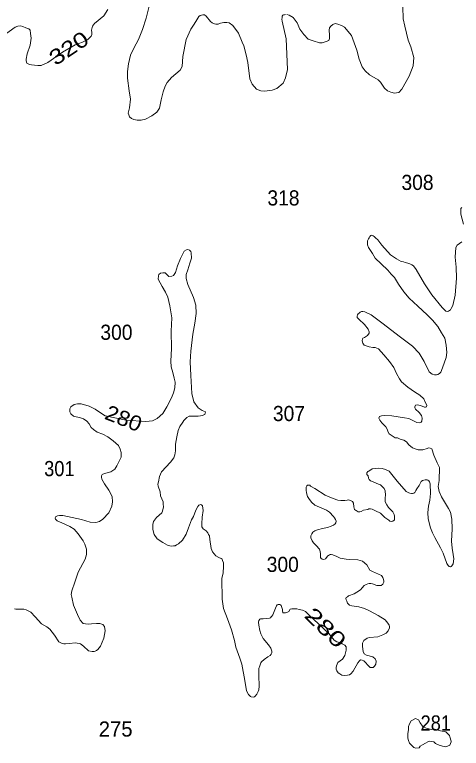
# Model space of a CAD drawing. Extents: x 445.4 to 500, y 8728.7 to 8784.
# Drawn here: x 488.21 to 492.93, y 8760.22 to 8767.97 of the extents above; entities that cross this region are included whole.
import ezdxf
from ezdxf.enums import TextEntityAlignment as Align

# ---------------------------------------------------------------- set-up
doc = ezdxf.new("R2010")
doc.units = 0
doc.header["$LTSCALE"] = 0.064
doc.layers.add('2', color=7, linetype='Continuous', lineweight=13)
doc.layers.add('21', color=7, linetype='Continuous')
doc.layers.add('61', color=7, linetype='Continuous')

msp = doc.modelspace()

# ---------------------------------------------------------------- linework, layer by layer
at = {"layer": '2'}
for points in [[(489.6381, 8768.086), (489.5993, 8767.9309), (489.5633, 8767.8091), (489.5185, 8767.7047), (489.4707, 8767.6136), (489.4334, 8767.5405), (489.414, 8767.4471), (489.402, 8767.365), (489.402, 8767.2949), (489.4214, 8767.1621), (489.435, 8767.0759), (489.4231, 8766.9819), (489.4111, 8766.9267), (489.4171, 8766.9073), (489.4246, 8766.8864), (489.444, 8766.8685), (489.4709, 8766.8581), (489.5067, 8766.8521), (489.5336, 8766.8521), (489.5485, 8766.8536), (489.5948, 8766.864), (489.662, 8766.8998), (489.7143, 8766.9357), (489.7427, 8766.9804), (489.7591, 8767.0669), (489.78, 8767.1505), (489.8013, 8767.2128), (489.8208, 8767.2516), (489.8686, 8767.3024), (489.9612, 8767.3814), (489.9821, 8767.4187), (489.9866, 8767.5232), (490.023, 8767.7048), (490.0708, 8767.8137), (490.1022, 8767.8555), (490.1261, 8767.8957), (490.1575, 8767.9465), (490.1694, 8767.9569), (490.1978, 8767.9659), (490.2157, 8767.9644), (490.2351, 8767.9509), (490.2799, 8767.8957), (490.2979, 8767.8793), (490.3232, 8767.8689), (490.3382, 8767.8674), (490.3606, 8767.8674), (490.3875, 8767.8763), (490.4024, 8767.8808), (490.4218, 8767.8838), (490.4353, 8767.8853), (490.4532, 8767.8853), (490.4786, 8767.8793), (490.5144, 8767.8525), (490.5742, 8767.7719), (490.616, 8767.6779), (490.6324, 8767.6391), (490.6578, 8767.5436), (490.6733, 8767.462), (490.6972, 8767.2874), (490.7196, 8767.2337), (490.7674, 8767.1785), (490.8107, 8767.1606), (490.8525, 8767.1591), (490.9332, 8767.1681), (490.9795, 8767.1875), (491.0467, 8767.2442), (491.0721, 8767.3009), (491.093, 8767.3889), (491.0855, 8767.5485), (491.0776, 8767.7107), (491.0358, 8767.8972), (491.0343, 8767.9181), (491.0358, 8767.9345), (491.0388, 8767.9494), (491.0448, 8767.9599), (491.0522, 8767.9643), (491.0627, 8767.9658), (491.0716, 8767.9673)], [(488.0492, 8767.7161), (488.2173, 8767.8364), (488.2441, 8767.8469), (488.274, 8767.8484), (488.2994, 8767.8424), (488.3293, 8767.829), (488.3606, 8767.8156), (488.3741, 8767.8021), (488.3801, 8767.7678), (488.3864, 8767.7191), (488.3744, 8767.646), (488.3431, 8767.5535), (488.3326, 8767.4953), (488.3341, 8767.4804), (488.3416, 8767.455), (488.367, 8767.4401), (488.3894, 8767.4356), (488.4207, 8767.4327), (488.4566, 8767.4312), (488.4924, 8767.4312), (488.5611, 8767.4625), (488.7165, 8767.5699), (488.8509, 8767.649), (488.9295, 8767.6752), (488.9833, 8767.7051), (489.0206, 8767.7394), (489.0251, 8767.7558), (489.0251, 8767.7782), (489.0236, 8767.8035), (489.0326, 8767.8438), (489.055, 8767.8751), (489.1521, 8767.9557), (489.1969, 8768.0214)], [(491.4316, 8767.6704), (491.46, 8767.6675), (491.5033, 8767.6824), (491.5287, 8767.6928), (491.5362, 8767.7152), (491.5362, 8767.751), (491.5332, 8767.8032), (491.5362, 8767.8271), (491.5496, 8767.8465), (491.5705, 8767.8629), (491.5974, 8767.8733), (491.6243, 8767.8659), (491.6631, 8767.8525), (491.6945, 8767.8345), (491.7677, 8767.7465), (491.8244, 8767.5929), (491.8505, 8767.495), (491.8819, 8767.4159), (491.9132, 8767.3741), (491.961, 8767.3309), (492.0506, 8767.2772), (492.076, 8767.2533), (492.1194, 8767.1921), (492.1507, 8767.1608), (492.186, 8767.1472), (492.2234, 8767.1383), (492.2443, 8767.1398), (492.2697, 8767.1457), (492.301, 8767.1786), (492.3787, 8767.3158), (492.419, 8767.4247), (492.4267, 8767.5134), (492.3968, 8767.6282), (492.3669, 8767.6983), (492.3311, 8767.846), (492.3161, 8767.9232), (492.3101, 8768.05)], [(491.0881, 8767.9688), (491.112, 8767.9629), (491.1523, 8767.9375), (491.1941, 8767.8793), (491.2225, 8767.8122), (491.2643, 8767.7555), (491.3121, 8767.7062), (491.3629, 8767.6898), (491.4316, 8767.6704)], [(492.9534, 8765.7557), (492.9253, 8765.8602), (492.9237, 8765.8836), (492.9237, 8765.8992), (492.9253, 8765.9179), (492.9347, 8765.9304)], [(492.5593, 8763.8564), (492.5453, 8763.8814), (492.5342, 8763.9106), (492.4905, 8763.9496), (492.4343, 8763.9839), (492.364, 8764.0323), (492.2969, 8764.09), (492.275, 8764.1196), (492.2438, 8764.1758), (492.2157, 8764.2397), (492.1701, 8764.3033), (492.1107, 8764.3735), (492.053, 8764.439), (492.0202, 8764.4515), (491.9936, 8764.453), (491.9546, 8764.4593), (491.9046, 8764.4749), (491.889, 8764.4983), (491.8859, 8764.5092), (491.8828, 8764.5263), (491.8859, 8764.5404), (491.889, 8764.5497), (491.9062, 8764.556), (491.9281, 8764.57), (491.939, 8764.5778), (491.9562, 8764.6043), (491.9562, 8764.6043), (491.9562, 8764.6184), (491.9437, 8764.6464), (491.9062, 8764.6932), (491.8453, 8764.7525), (491.8297, 8764.7696), (491.8281, 8764.7837), (491.8312, 8764.7961), (491.8406, 8764.8055), (491.85, 8764.8149), (491.8609, 8764.8242), (491.875, 8764.832), (491.889, 8764.832), (491.9109, 8764.8273), (491.9765, 8764.7977), (492.0904, 8764.7119), (492.2856, 8764.5591), (492.4152, 8764.464), (492.4845, 8764.3912), (492.5361, 8764.3054), (492.5891, 8764.1932), (492.6204, 8764.1682), (492.6469, 8764.162), (492.6656, 8764.1635), (492.6797, 8764.1651), (492.6984, 8764.176), (492.714, 8764.1916), (492.7312, 8764.2353), (492.7687, 8764.346), (492.7764, 8764.3987), (492.7702, 8764.4751), (492.7546, 8764.5484), (492.7187, 8764.6077), (492.6812, 8764.6747), (492.6265, 8764.7402), (492.5672, 8764.7979), (492.4714, 8764.8896), (492.3778, 8764.9723), (492.3216, 8765.0393), (492.2653, 8765.1189), (492.2232, 8765.1922), (492.1873, 8765.2265), (492.1545, 8765.267), (492.0838, 8765.3352), (492.0182, 8765.396), (491.9901, 8765.4459), (491.9495, 8765.5068), (491.9401, 8765.5348), (491.9386, 8765.5582), (491.9401, 8765.5785), (491.9479, 8765.5988), (491.9573, 8765.6112), (491.9636, 8765.6222), (491.9729, 8765.6346), (491.9854, 8765.6362), (491.9979, 8765.63), (492.0104, 8765.6222), (492.0245, 8765.6097), (492.0463, 8765.5879), (492.09, 8765.5333), (492.1829, 8765.431), (492.2453, 8765.3889), (492.2953, 8765.3608), (492.3187, 8765.3546), (492.3375, 8765.3484), (492.364, 8765.3421), (492.3859, 8765.3359), (492.4062, 8765.325), (492.4233, 8765.3125), (492.4514, 8765.2766), (492.5404, 8765.1253), (492.6162, 8765.0065), (492.7254, 8764.874), (492.766, 8764.8366), (492.7848, 8764.8334)], [(492.7848, 8764.8334), (492.7957, 8764.8366), (492.8144, 8764.849), (492.8144, 8764.849), (492.8207, 8764.8631), (492.841, 8764.8943), (492.866, 8765.0034), (492.88, 8765.1828), (492.8738, 8765.2994), (492.866, 8765.4054), (492.8722, 8765.5083), (492.8863, 8765.5317), (492.9331, 8765.5676)], [(488.9699, 8762.3213), (488.9539, 8762.3754), (488.9344, 8762.4083), (488.8818, 8762.4831), (488.8387, 8762.5325), (488.7941, 8762.5627), (488.7096, 8762.5994), (488.6602, 8762.6217), (488.6443, 8762.6376), (488.6411, 8762.6487), (488.6443, 8762.6615), (488.6554, 8762.6694), (488.6634, 8762.6726), (488.6841, 8762.6758), (488.7208, 8762.6758), (488.9162, 8762.6347), (489.0103, 8762.6077), (489.0693, 8762.6029), (489.1075, 8762.6156), (489.1426, 8762.6395), (489.2064, 8762.7064), (489.2382, 8762.7764), (489.2462, 8762.8226), (489.2398, 8762.8783), (489.2063, 8762.9448), (489.1617, 8763.0117), (489.1314, 8763.0594), (489.1282, 8763.0817), (489.1282, 8763.0945), (489.1362, 8763.1088), (489.1601, 8763.1199), (489.2287, 8763.139), (489.2701, 8763.1677), (489.2924, 8763.2027), (489.3355, 8763.2935), (489.337, 8763.3412), (489.3259, 8763.3779), (489.3081, 8763.4171), (489.2507, 8763.4648), (489.1949, 8763.5094), (489.1439, 8763.5349), (489.0818, 8763.5588), (489.0435, 8763.5843), (489.018, 8763.605), (488.9973, 8763.6463), (488.9734, 8763.675), (488.9399, 8763.6973), (488.9064, 8763.7084), (488.8331, 8763.7276), (488.806, 8763.7498), (488.7948, 8763.7721), (488.7948, 8763.8024), (488.8044, 8763.8263), (488.8395, 8763.8501), (488.8761, 8763.8581), (488.9144, 8763.8581), (488.9973, 8763.831), (489.0626, 8763.8008), (489.1168, 8763.761), (489.1678, 8763.7307), (489.391, 8763.6846), (489.5958, 8763.6705), (489.666, 8763.6769), (489.717, 8763.7008), (489.7776, 8763.7533), (489.819, 8763.8265), (489.8669, 8763.9217), (489.8908, 8763.9711), (489.902, 8764.0252), (489.9068, 8764.0857), (489.8956, 8764.1287), (489.8813, 8764.1876), (489.8653, 8764.2481), (489.8621, 8764.3086), (489.867, 8764.4403), (489.8638, 8764.625), (489.8734, 8764.7644), (489.8511, 8764.8933), (489.8303, 8764.9841), (489.8032, 8765.0366), (489.7698, 8765.0955), (489.7283, 8765.1748), (489.7299, 8765.2082), (489.7331, 8765.221), (489.7506, 8765.2353), (489.7761, 8765.2417), (489.7873, 8765.2417), (489.8001, 8765.2385), (489.8256, 8765.2146), (489.8399, 8765.2003), (489.8734, 8765.2066), (489.8734, 8765.2066), (489.8877, 8765.2114), (489.9116, 8765.2432), (489.9308, 8765.3149), (489.9626, 8765.3913), (490.0025, 8765.4677), (490.028, 8765.4821), (490.0392, 8765.4853), (490.0599, 8765.4789), (490.071, 8765.4662)], [(490.071, 8765.4662), (490.0758, 8765.4518), (490.0791, 8765.3937), (490.0632, 8765.3427), (490.0408, 8765.2727), (490.0233, 8765.2233), (490.0233, 8765.1803), (490.0393, 8765.1182), (490.0998, 8764.9797), (490.1263, 8764.8997), (490.1285, 8764.8115), (490.1136, 8764.7098), (490.0924, 8764.5932), (490.0733, 8764.4119), (490.0669, 8764.2996), (490.0733, 8764.1554), (490.0818, 8763.9657), (490.103, 8763.8767), (490.1497, 8763.8131), (490.1921, 8763.7856), (490.2261, 8763.7707), (490.2261, 8763.7707), (490.2197, 8763.7453), (490.2197, 8763.7453), (490.1921, 8763.7347), (490.173, 8763.7284), (490.1497, 8763.7262), (490.1178, 8763.7262), (490.086, 8763.7262), (490.0542, 8763.7262), (490.0287, 8763.7114), (489.9969, 8763.6796), (489.9863, 8763.6627), (489.9546, 8763.6174), (489.9393, 8763.5759), (489.9251, 8763.507), (489.9109, 8763.4306), (489.9087, 8763.3607), (489.9029, 8763.3174), (489.893, 8763.2879), (489.8591, 8763.2388), (489.764, 8763.1393), (489.741, 8763.0891), (489.7295, 8763.0335), (489.724, 8763.0095), (489.7262, 8762.9865), (489.747, 8762.9286), (489.7524, 8762.886), (489.7787, 8762.8216), (489.7809, 8762.7964), (489.782, 8762.768), (489.7743, 8762.7243), (489.7645, 8762.707), (489.711, 8762.6568), (489.6781, 8762.6153), (489.6694, 8762.5825), (489.6705, 8762.5279), (489.6847, 8762.4776), (489.7153, 8762.4318), (489.7755, 8762.3924), (489.8258, 8762.364), (489.8663, 8762.3542), (489.8892, 8762.3553), (489.9056, 8762.3575), (489.9209, 8762.3662), (489.9417, 8762.3793), (489.9855, 8762.4154), (490.0237, 8762.4809), (490.0489, 8762.5454), (490.0806, 8762.6328), (490.1016, 8762.6652), (490.1268, 8762.7329), (490.1465, 8762.7733), (490.1552, 8762.7854), (490.1673, 8762.7897), (490.1793, 8762.7919), (490.1793, 8762.7919), (490.1869, 8762.7876), (490.1946, 8762.7788), (490.199, 8762.7548), (490.2023, 8762.7318), (490.1935, 8762.659), (490.188, 8762.5891), (490.1902, 8762.5574), (490.2023, 8762.5377), (490.2329, 8762.517), (490.2529, 8762.4935), (490.2606, 8762.4782), (490.2682, 8762.4608), (490.2737, 8762.4247), (490.2857, 8762.3286), (490.3021, 8762.2925), (490.3196, 8762.2707), (490.3382, 8762.2499), (490.3678, 8762.2324), (490.3929, 8762.2237), (490.4028, 8762.2161), (490.4082, 8762.203), (490.4159, 8762.1789), (490.4192, 8762.1376), (490.4126, 8762.0732)], [(492.4131, 8762.9105), (492.4293, 8762.9146), (492.4385, 8762.9217), (492.4506, 8762.9399), (492.4598, 8762.9592), (492.4831, 8762.9937), (492.5035, 8763.0353), (492.5207, 8763.0454), (492.5492, 8763.0525), (492.5583, 8763.0546), (492.5685, 8763.0546), (492.5756, 8763.0505), (492.5857, 8763.0434), (492.5939, 8763.0322), (492.601, 8763.012), (492.605, 8762.9105), (492.5959, 8762.8405), (492.5812, 8762.7747), (492.5751, 8762.7079), (492.5787, 8762.6411), (492.6047, 8762.5469), (492.6243, 8762.4925), (492.651, 8762.4464), (492.7079, 8762.3364), (492.7382, 8762.2784), (492.7764, 8762.1705), (492.7915, 8762.1489), (492.7973, 8762.1432), (492.8023, 8762.1374), (492.8102, 8762.1338), (492.8138, 8762.1353), (492.8225, 8762.1381), (492.8297, 8762.1446), (492.8419, 8762.1662), (492.8491, 8762.2194), (492.8448, 8762.2651), (492.8333, 8762.3313), (492.8239, 8762.4075), (492.8312, 8762.5362), (492.8289, 8762.6379), (492.8152, 8762.7132), (492.7923, 8762.7497), (492.7216, 8762.8728), (492.6965, 8762.9321), (492.685, 8762.9845), (492.6942, 8763.0484), (492.6987, 8763.1829), (492.6756, 8763.2329), (492.638, 8763.3158), (492.6185, 8763.3819), (492.6004, 8763.3897), (492.5835, 8763.3936), (492.5689, 8763.3861), (492.5236, 8763.372), (492.4971, 8763.3705), (492.4736, 8763.3705), (492.4424, 8763.3798), (492.4127, 8763.3907), (492.3737, 8763.4219), (492.3501, 8763.4541), (492.3205, 8763.4712), (492.2845, 8763.4837), (492.2705, 8763.4915), (492.2564, 8763.4977), (492.2299, 8763.4977), (492.1674, 8763.5398), (492.1534, 8763.5632), (492.1487, 8763.5819), (492.1315, 8763.6147), (492.0894, 8763.6552), (492.0675, 8763.6849), (492.0597, 8763.7036), (492.0659, 8763.7223), (492.0659, 8763.7223), (492.0847, 8763.7285), (492.1128, 8763.7317), (492.1955, 8763.7301), (492.3283, 8763.7083), (492.3751, 8763.702), (492.4251, 8763.6771), (492.461, 8763.6584), (492.4828, 8763.6552), (492.5063, 8763.6646), (492.5063, 8763.6646), (492.5109, 8763.674), (492.5141, 8763.7036), (492.5078, 8763.7348), (492.4844, 8763.7644), (492.4454, 8763.8003), (492.4391, 8763.8128), (492.4391, 8763.8237), (492.4454, 8763.8424), (492.4454, 8763.8424), (492.4641, 8763.8455), (492.4969, 8763.8377), (492.539, 8763.8221), (492.5515, 8763.8206), (492.5609, 8763.8252), (492.5656, 8763.8393), (492.5656, 8763.8393), (492.5593, 8763.8564)], [(491.3617, 8762.5), (491.3832, 8762.5156), (491.4086, 8762.5253), (491.4642, 8762.541), (491.5143, 8762.5517), (491.5542, 8762.565), (491.5806, 8762.5762), (491.5979, 8762.5904), (491.604, 8762.6015), (491.607, 8762.6167), (491.5989, 8762.634), (491.5888, 8762.6512), (491.5776, 8762.6675), (491.538, 8762.7111), (491.5065, 8762.7324), (491.4303, 8762.7639), (491.3826, 8762.7862), (491.347, 8762.8166), (491.3204, 8762.8561), (491.3062, 8762.8794), (491.294, 8762.918), (491.2889, 8762.9443), (491.2889, 8762.9616), (491.29, 8762.9707), (491.291, 8762.9778), (491.2991, 8762.99), (491.3052, 8762.9961), (491.3113, 8762.9981), (491.3296, 8762.9961), (491.3377, 8762.9859), (491.383, 8762.962), (491.4907, 8762.891), (491.575, 8762.8565), (491.6248, 8762.8403), (491.6583, 8762.8362), (491.6979, 8762.8362), (491.7233, 8762.8403), (491.7375, 8762.8413), (491.7588, 8762.8372), (491.767, 8762.8332), (491.7791, 8762.8251), (491.7923, 8762.8058), (491.7944, 8762.7693), (491.7974, 8762.753), (491.8015, 8762.7419), (491.8106, 8762.7338), (491.8188, 8762.7297), (491.8411, 8762.7175), (491.858, 8762.7159), (491.8712, 8762.72), (491.8965, 8762.7322), (491.9423, 8762.7423), (491.9534, 8762.7474), (491.9687, 8762.7484), (491.9869, 8762.7433), (492.0245, 8762.7251), (492.0743, 8762.7027), (492.122, 8762.6551), (492.1627, 8762.6277), (492.1759, 8762.6175), (492.1931, 8762.6145), (492.2063, 8762.6175), (492.2185, 8762.6277), (492.2185, 8762.6277), (492.2226, 8762.6327), (492.2236, 8762.647), (492.2246, 8762.6693), (492.2185, 8762.6881), (492.2053, 8762.7155), (492.1617, 8762.7632), (492.1434, 8762.7916), (492.1292, 8762.8139), (492.1241, 8762.8251), (492.1241, 8762.8464), (492.1241, 8762.8626), (492.1281, 8762.8931), (492.1251, 8762.9377), (492.1158, 8762.9607), (492.0904, 8762.9881), (492.0772, 8763.0013), (492.0558, 8763.0084), (491.9969, 8763.0317), (491.9685, 8763.0439), (491.9563, 8763.0571), (491.9492, 8763.0713), (491.9441, 8763.0946), (491.9319, 8763.1119), (491.9329, 8763.1281), (491.9421, 8763.1403), (491.9522, 8763.1464), (491.9888, 8763.1697), (492.0579, 8763.1768), (492.0944, 8763.1738), (492.129, 8763.1646), (492.1676, 8763.1454), (492.2526, 8763.0414), (492.346, 8762.9318), (492.3765, 8762.9156), (492.3867, 8762.9115), (492.4029, 8762.9105), (492.4131, 8762.9105)], [(491.7482, 8760.9951), (491.7632, 8761.0051), (491.7865, 8761.0317), (491.8348, 8761.1199), (491.8532, 8761.1432), (491.8648, 8761.1515), (491.8831, 8761.1498), (491.8831, 8761.1498), (491.8998, 8761.1432), (491.9181, 8761.1249), (491.9414, 8761.0983), (491.9681, 8761.0717), (491.9864, 8761.0717), (491.9981, 8761.0733), (492.0131, 8761.0866), (492.0266, 8761.1078), (492.0299, 8761.1394), (492.0199, 8761.1643), (491.9949, 8761.1859), (491.9267, 8761.2026), (491.9017, 8761.2176), (491.8917, 8761.2392), (491.8883, 8761.2658), (491.8867, 8761.2957), (491.8867, 8761.3274), (491.8998, 8761.3588), (491.9361, 8761.3805), (491.9602, 8761.3893), (492.0479, 8761.3974), (492.0994, 8761.4183), (492.1356, 8761.4343), (492.1583, 8761.4598), (492.1719, 8761.4903), (492.1695, 8761.5048), (492.1671, 8761.5192), (492.1518, 8761.5393), (492.1245, 8761.5739), (492.0504, 8761.6221), (491.9611, 8761.6687), (491.906, 8761.6934), (491.848, 8761.7135), (491.774, 8761.7248), (491.7466, 8761.732), (491.7281, 8761.7505), (491.7185, 8761.7738), (491.712, 8761.7883), (491.7112, 8761.7995), (491.7145, 8761.8108), (491.7257, 8761.8188), (491.7386, 8761.8276), (491.7989, 8761.8509), (491.8263, 8761.867), (491.8649, 8761.8927), (491.8834, 8761.9144), (491.9039, 8761.9368), (491.9253, 8761.9486), (491.9419, 8761.957), (491.9562, 8761.9593), (491.9728, 8761.9593), (491.9895, 8761.9546), (492.0382, 8761.9391), (492.0824, 8761.9368), (492.1021, 8761.9522), (492.1109, 8761.9741), (492.1109, 8761.9851), (492.1087, 8762.0004), (492.0999, 8762.0224), (492.0868, 8762.0443), (491.9923, 8762.086), (491.9637, 8762.1014), (491.9308, 8762.1562), (491.8868, 8762.1957), (491.838, 8762.2097), (491.7532, 8762.2121), (491.7118, 8762.2151), (491.6935, 8762.218), (491.6511, 8762.2279), (491.6142, 8762.2443), (491.5713, 8762.2616), (491.5555, 8762.2645), (491.5432, 8762.264), (491.5368, 8762.2611), (491.5279, 8762.2557), (491.5205, 8762.2512), (491.4939, 8762.2207), (491.4771, 8762.2133), (491.4682, 8762.2148), (491.4589, 8762.2172), (491.4505, 8762.2217), (491.4426, 8762.2335), (491.4406, 8762.2498), (491.4406, 8762.2729), (491.4391, 8762.2966), (491.4299, 8762.3228), (491.3967, 8762.3589), (491.3684, 8762.3891), (491.3528, 8762.4106), (491.3411, 8762.4418), (491.3401, 8762.4623), (491.3489, 8762.4837), (491.3617, 8762.5)], [(488.2086, 8761.6924), (488.223, 8761.6876), (488.2421, 8761.6892), (488.2565, 8761.6892), (488.3075, 8761.6876), (488.333, 8761.6796), (488.384, 8761.6558), (488.4286, 8761.6064), (488.4956, 8761.5332), (488.5513, 8761.5013), (488.5848, 8761.4758), (488.6321, 8761.4129), (488.6799, 8761.3428), (488.7133, 8761.3253), (488.7293, 8761.3221), (488.7484, 8761.3221), (488.7899, 8761.3253), (488.852, 8761.3317), (488.8919, 8761.3269), (488.9078, 8761.3205), (488.9381, 8761.2982), (488.9907, 8761.2473), (489.029, 8761.2393), (489.0513, 8761.2409), (489.0624, 8761.2457), (489.0752, 8761.252), (489.0911, 8761.2632), (489.1166, 8761.2966), (489.1533, 8761.381), (489.169, 8761.4587), (489.1594, 8761.5032), (489.1419, 8761.5255), (489.1116, 8761.5383), (489.0765, 8761.5367), (489.0223, 8761.5319), (488.9936, 8761.5303), (488.9602, 8761.5319), (488.9362, 8761.5383), (488.9028, 8761.5717), (488.8741, 8761.6322), (488.8326, 8761.7309), (488.8151, 8761.8137), (488.8087, 8761.8424), (488.8167, 8761.8822), (488.8487, 8761.9742), (488.8822, 8762.0777), (488.9555, 8762.2162), (488.9714, 8762.264), (488.9699, 8762.3213)], [(490.4126, 8762.0732), (490.4006, 8762.0131), (490.4039, 8761.7941), (490.4192, 8761.6958), (490.4581, 8761.5865), (490.5021, 8761.4681), (490.5325, 8761.3574), (490.5481, 8761.2874), (490.5883, 8761.1691), (490.6097, 8761.1078), (490.6419, 8760.935), (490.6614, 8760.8241), (490.6818, 8760.7852), (490.7023, 8760.7648), (490.7091, 8760.7609), (490.7324, 8760.757), (490.7441, 8760.7619), (490.7509, 8760.7677), (490.7685, 8760.7891), (490.784, 8760.8183), (490.7909, 8760.8358), (490.7939, 8760.8733), (490.789, 8760.9862), (490.79, 8761.061), (490.8007, 8761.0912), (490.8124, 8761.1204), (490.8173, 8761.1301), (490.8475, 8761.1571), (490.8865, 8761.1844), (490.9089, 8761.198), (490.9205, 8761.2126), (490.9274, 8761.2281), (490.9274, 8761.2456), (490.9157, 8761.2748), (490.8923, 8761.3118), (490.8368, 8761.3779), (490.8125, 8761.4285), (490.8006, 8761.462), (490.7909, 8761.5194), (490.787, 8761.5505), (490.7899, 8761.5671), (490.7957, 8761.5729), (490.8026, 8761.5807), (490.8094, 8761.5855), (490.8357, 8761.5865), (490.8668, 8761.5904), (490.9028, 8761.5933), (490.9136, 8761.5972), (490.9223, 8761.6069), (490.9272, 8761.6137), (490.9395, 8761.6279), (490.9668, 8761.6999), (490.9775, 8761.7242), (490.9843, 8761.7339), (490.996, 8761.7378), (490.996, 8761.7378), (491.0116, 8761.7378), (491.0116, 8761.7378), (491.0194, 8761.7339), (491.0262, 8761.7252), (491.0379, 8761.694), (491.0398, 8761.6833), (491.0408, 8761.6736), (491.0418, 8761.6658), (491.0427, 8761.6561), (491.0457, 8761.6503), (491.0603, 8761.6483), (491.071, 8761.6493), (491.0875, 8761.6532), (491.108, 8761.6639), (491.1226, 8761.6872), (491.1381, 8761.6921), (491.1615, 8761.6921), (491.1907, 8761.6921), (491.2151, 8761.6853), (491.2528, 8761.6758), (491.2828, 8761.6625), (491.3145, 8761.6326), (491.5301, 8761.4306), (491.5851, 8761.3591), (491.615, 8761.3424), (491.6567, 8761.3341), (491.6717, 8761.3208), (491.6983, 8761.3075), (491.7116, 8761.2908), (491.7133, 8761.2809), (491.7116, 8761.2559), (491.6999, 8761.1997), (491.6733, 8761.1598), (491.6267, 8761.1249), (491.61, 8761.09), (491.6067, 8761.0717), (491.6067, 8761.0534), (491.6133, 8761.0384), (491.62, 8761.0267), (491.63, 8761.0168), (491.6466, 8761.0034), (491.6666, 8760.9918), (491.6949, 8760.9885), (491.7283, 8760.9918), (491.7482, 8760.9951)]]:
    msp.add_lwpolyline(points, dxfattribs=at)
msp.add_lwpolyline([(492.5191, 8760.4512), (492.496, 8760.4858), (492.4767, 8760.5205), (492.4459, 8760.532), (492.3997, 8760.507), (492.3805, 8760.4781), (492.3709, 8760.4473), (492.3728, 8760.4166), (492.3651, 8760.3704), (492.3651, 8760.3242), (492.3728, 8760.3011), (492.3824, 8760.2722), (492.4017, 8760.251), (492.4267, 8760.2279), (492.4498, 8760.2183), (492.4825, 8760.2241), (492.496, 8760.2414), (492.521, 8760.2549), (492.5499, 8760.2722), (492.5768, 8760.2857), (492.598, 8760.2934), (492.6384, 8760.2876), (492.6557, 8760.2683), (492.6962, 8760.251), (492.7308, 8760.2414), (492.7674, 8760.2356), (492.8097, 8760.253), (492.8232, 8760.2857), (492.8232, 8760.2953), (492.8097, 8760.3396), (492.8039, 8760.355), (492.7654, 8760.3915), (492.7077, 8760.4031), (492.648, 8760.4204), (492.6192, 8760.4166), (492.5691, 8760.4281), (492.5326, 8760.4416)], close=True, dxfattribs=at)

# ---------------------------------------------------------------- texts
at = {"layer": '21'}
for s, width, p in [('308', 0.95, (492.2971, 8766.1153)), ('318', 0.95, (490.881, 8765.9514)), ('300', 0.95, (489.1168, 8764.5325)), ('307', 0.95, (490.9393, 8763.6744)), ('301', 0.9, (488.5233, 8763.0927)), ('300', 0.95, (490.8737, 8762.081)), ('281', 0.9, (492.4988, 8760.4062))]:
    msp.add_text(s, height=0.16, dxfattribs=dict(at, width=width)).set_placement(p)
msp.add_text('275', height=0.16, dxfattribs=at).set_placement((489.0999, 8760.3423))
at = {"layer": '61'}
for s, rotation, width, p in [('320', 34.032, 1.25, (488.8287, 8767.5462)), ('280', 338.421, 1.1, (489.3335, 8763.6288)), ('280', 315.839, 1.4, (491.4397, 8761.4356))]:
    msp.add_text(s, height=0.16, rotation=rotation, dxfattribs=dict(at, width=width)).set_placement(p, align=Align.CENTER)

doc.saveas('drawing.dxf')
